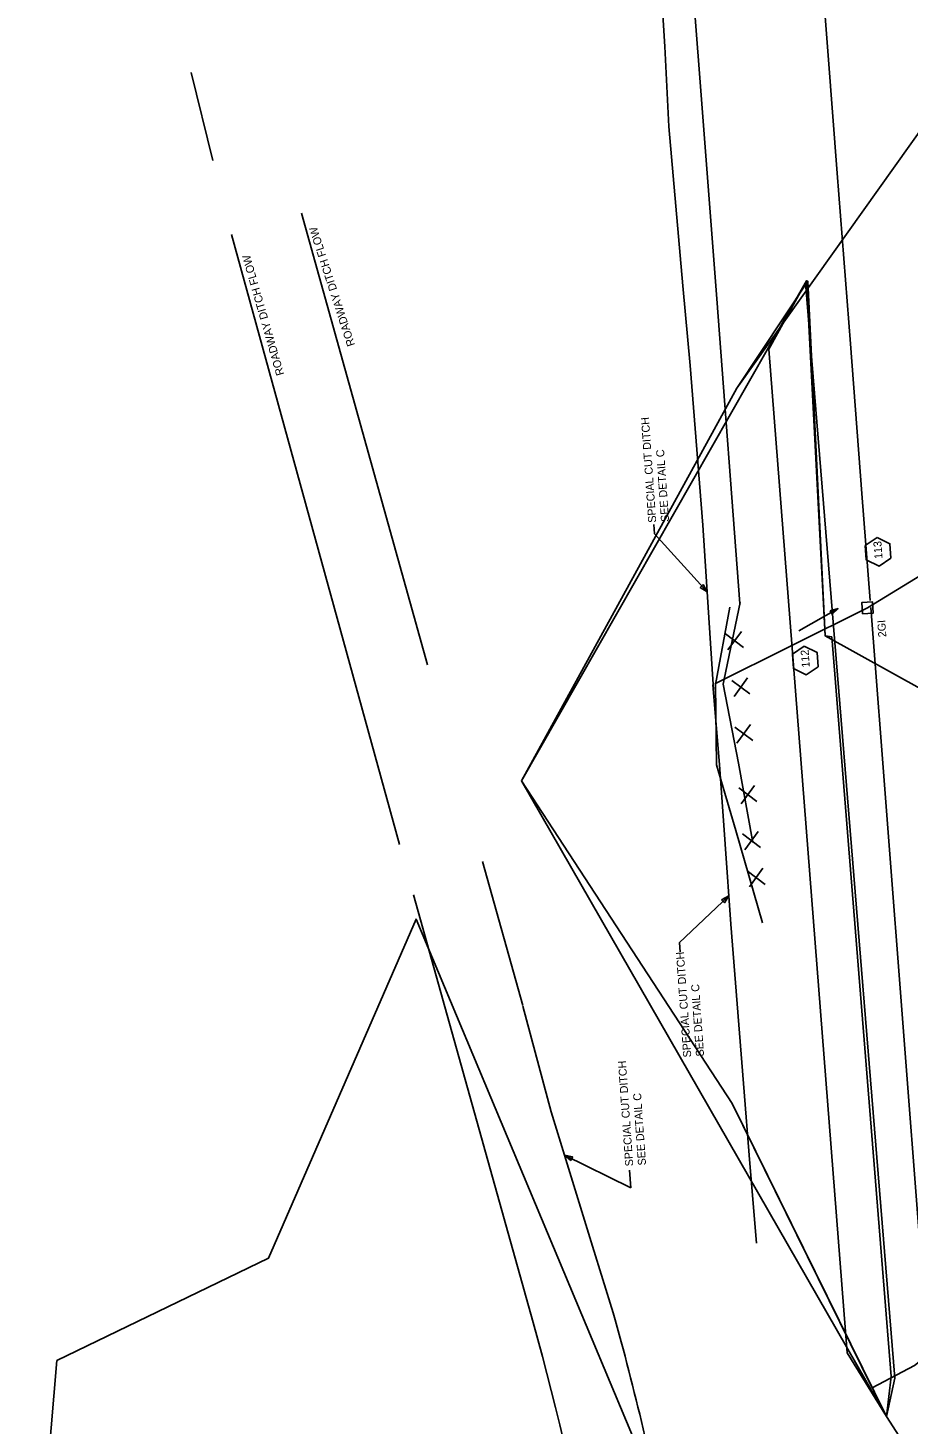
# Model space of a CAD drawing. Extents: x 2384780 to 2405432, y 547869 to 573706.
# Drawn here: x 2399727 to 2400276, y 566101 to 566973 of the extents above; entities that cross this region are included whole.
import ezdxf

# ---------------------------------------------------------------- set-up
doc = ezdxf.new("R2010")
doc.units = 0
for name, color, linetype in [('Old_Level_1', 7, 'Continuous'), ('Old_Level_18', 7, 'Continuous'), ('Old_Level_19', 7, 'Continuous'), ('Old_Level_5', 7, 'Continuous'), ('Old_Level_62', 7, 'Continuous'), ('Old_Level_63', 7, 'Continuous'), ('Prop Drainage Box Number Symbol CELL', 7, 'Continuous'), ('Prop Pipe RCP 24in', 7, 'Continuous'), ('Prop Special Cut Ditch Detail CELL', 7, 'Continuous')]:
    doc.layers.add(name, color=color, linetype=linetype)

msp = doc.modelspace()

# ---------------------------------------------------------------- linework, layer by layer
at = {"layer": 'Old_Level_1'}
msp.add_lwpolyline([(2400247.9, 566607), (2400247.41, 566614.01), (2400254.1, 566614.48), (2400254.59, 566607.47)], close=True, dxfattribs=at)
at = {"layer": 'Old_Level_18'}
for points in [[(2400161.4, 566566.2), (2400171.51, 566614.03)], [(2400161.4, 566566.2), (2400160.75, 566563.15), (2400170.31, 566513.7), (2400179.4, 566464.21)], [(2400035.8, 566361.78), (2400053.53, 566295.75), (2400079.17, 566211.97), (2400092.24, 566170.26)]]:
    msp.add_lwpolyline(points, dxfattribs=at)
at = {"layer": 'Old_Level_19'}
for p, q in [((2399828.71, 566945.27), (2399842.16, 566890.32)), ((2399976.23, 566575.2), (2399897.48, 566857.38)), ((2399958.78, 566462.9), (2399853.81, 566844.08)), ((2400316.16, 565790.8), (2400253, 566610.89)), ((2400010.55, 566452.25), (2400035.67, 566362.23)), ((2399967.57, 566431.4), (2400042.13, 566164.26))]:
    msp.add_line(p, q, dxfattribs=at)
for points in [[(2400173.94, 567637.33), (2400177.9, 567585.99), (2400181.5, 567539.26), (2400187.17, 567465.59), (2400193.34, 567385.47), (2400200.55, 567291.83), (2400205.06, 567233.32), (2400210.62, 567161.03), (2400216.02, 567091.02), (2400220.77, 567029.37), (2400226.43, 566955.87), (2400232.09, 566882.34), (2400240.3, 566775.68), (2400247.51, 566682.17), (2400252.65, 566615.34)], [(2400133.12, 567112.52), (2400156.9, 566803.75), (2400171.19, 566613.49)]]:
    msp.add_lwpolyline(points, dxfattribs=at)
for centre, radius, start, end in [((2398183.56, 565640.71), 1980.77, 11.17331, 15.50611), ((2398139.82, 565633.35), 1975, 5.37234, 15.59355)]:
    msp.add_arc(centre, radius, start, end, dxfattribs=at)
at = {"layer": 'Old_Level_5'}
for p, q in [((2400117.88, 566657.08), (2400117.48, 566662.74)), ((2400150.85, 566620.69), (2400117.88, 566657.08)), ((2400232.56, 566610.26), (2400208.03, 566596.41)), ((2400164.37, 566430.8), (2400133.44, 566401.35)), ((2400133.54, 566401.44), (2400133.94, 566395.7)), ((2400061.81, 566268.69), (2400103.15, 566248.35)), ((2400103.15, 566248.35), (2400102.38, 566259.42))]:
    msp.add_line(p, q, dxfattribs=at)
for points in [[(2400148.42, 566625.24), (2400150.85, 566620.69), (2400146.57, 566623.56)], [(2400227.6, 566608.89), (2400232.56, 566610.26), (2400228.83, 566606.72)], [(2400159.88, 566428.26), (2400164.37, 566430.8), (2400161.61, 566426.45)], [(2400065.74, 566265.36), (2400061.81, 566268.69), (2400066.85, 566267.61)]]:
    msp.add_lwpolyline(points, close=True, dxfattribs=at)
at = {"layer": 'Old_Level_62'}
msp.add_lwpolyline([(2400440.43, 567218), (2400317.07, 566955.7), (2400169.34, 566748.06), (2400034.82, 566502.63), (2400166.54, 566301.02), (2400262.78, 566105.47), (2400571.01, 565626.1)], dxfattribs=at)
for points in [[(2400228.78, 566592.61), (2400265.67, 566130.41), (2400262.78, 566105.47), (2400034.82, 566502.63), (2400212.89, 566815.19), (2400224.49, 566593.36)], [(2400253.97, 566123.38), (2400166.54, 566301.02), (2400034.82, 566502.63), (2400169.34, 566748.06), (2400213.68, 566814.89), (2400224.49, 566593.36), (2400410.03, 566490.27), (2400451.8, 566363.65), (2400374.13, 566238.93), (2400362.99, 566203.35), (2400280.39, 566137.4)], [(2400262.78, 566105.47), (2400267.96, 566129.36), (2400212.35, 566813.79), (2400189.31, 566772.45), (2400238.19, 566145.26)], [(2400339.33, 564522.76), (2400485.81, 564616.68), (2400370.09, 564992.65), (2400258.07, 565392.28), (2400234.01, 565684.68), (2400121.91, 566051.12), (2399969.11, 566416.3), (2399876.99, 566204.34), (2399744.83, 566140.38), (2399726.75, 565925.09), (2400029.82, 565489.59), (2400131.32, 565573.2), (2400194.24, 564735.04)]]:
    msp.add_lwpolyline(points, close=True, dxfattribs=at)
at = {"layer": 'Old_Level_63'}
for p, q in [((2400173.62, 566586.02), (2400162.35, 566594.47)), ((2400163.77, 566584.45), (2400172.2, 566596.04)), ((2400177.51, 566557), (2400166.25, 566565.45)), ((2400167.66, 566555.43), (2400176.1, 566567.02)), ((2400179.29, 566527.76), (2400168.02, 566536.22)), ((2400169.43, 566526.2), (2400177.87, 566537.78)), ((2400181.9, 566489.82), (2400170.64, 566498.27)), ((2400172.05, 566488.25), (2400180.49, 566499.84)), ((2400184.12, 566461.04), (2400172.85, 566469.49)), ((2400174.27, 566459.47), (2400182.7, 566471.06)), ((2400187.13, 566437.97), (2400175.86, 566446.42)), ((2400177.28, 566436.4), (2400185.71, 566447.99))]:
    msp.add_line(p, q, dxfattribs=at)
msp.add_lwpolyline([(2400185.3, 566413.93), (2400168.66, 566471.62), (2400156.58, 566512.74), (2400155.98, 566562.82), (2400165.06, 566611.13)], dxfattribs=at)
at = {"layer": 'Prop Drainage Box Number Symbol CELL'}
for points in [[(2400256.91, 566654.71), (2400249.49, 566649.7), (2400250.12, 566640.78), (2400258.16, 566636.85), (2400265.58, 566641.86), (2400264.95, 566650.79)], [(2400211.5, 566586.76), (2400204.09, 566581.75), (2400204.71, 566572.82), (2400212.75, 566568.9), (2400220.17, 566573.91), (2400219.55, 566582.83)]]:
    msp.add_lwpolyline(points, close=True, dxfattribs=at)
at = {"layer": 'Prop Pipe RCP 24in'}
for p, q in [((2400251, 566610.74), (2400342.01, 566666.6)), ((2400155.63, 566563.24), (2400251, 566610.74))]:
    msp.add_line(p, q, dxfattribs=at)
at = {"layer": 'Prop Special Cut Ditch Detail CELL'}
for points in [[(2400107.55, 567160.9), (2400112.89, 567111.15), (2400117.45, 567061.35), (2400121.35, 567011.5), (2400124.48, 566961.6), (2400126.87, 566911.64), (2400131.31, 566861.83), (2400135.75, 566812.02), (2400140.19, 566762.21), (2400148.12, 566662.52), (2400154.83, 566559.79)], [(2400181.6, 566213.76), (2400177.59, 566263.6), (2400173.58, 566313.44), (2400169.58, 566363.29), (2400165.57, 566413.13), (2400162.17, 566463.01), (2400158.52, 566512.88), (2400154.41, 566562.71)]]:
    msp.add_lwpolyline(points, dxfattribs=at)

# ---------------------------------------------------------------- texts
at = {"layer": 'Old_Level_1'}
msp.add_text('2GI', height=5, rotation=93.99991, dxfattribs=at).set_placement((2400262.74, 566592.58))
at = {"layer": 'Old_Level_19'}
for rotation, p in [(107.93913, (2399931.06, 566775.09)), (105.98111, (2399886.78, 566756.72))]:
    msp.add_text('ROADWAY DITCH FLOW', height=5, rotation=rotation, dxfattribs=at).set_placement(p)
at = {"layer": 'Old_Level_5'}
for s, p in [('SPECIAL CUT DITCH', (2400119.09, 566664.12)), ('SEE DETAIL C', (2400127.07, 566664.68)), ('SPECIAL CUT DITCH', (2400140.95, 566330.03)), ('SEE DETAIL C', (2400148.93, 566330.59)), ('SPECIAL CUT DITCH', (2400104.73, 566261.97)), ('SEE DETAIL C', (2400112.71, 566262.52))]:
    msp.add_text(s, height=5, rotation=93.99991, dxfattribs=at).set_placement(p)
at = {"layer": 'Prop Drainage Box Number Symbol CELL'}
for s, p in [('113', (2400260.34, 566641.49)), ('112', (2400214.93, 566573.62))]:
    msp.add_text(s, height=5, rotation=94.00053, dxfattribs=at).set_placement(p)

doc.saveas('drawing.dxf')
